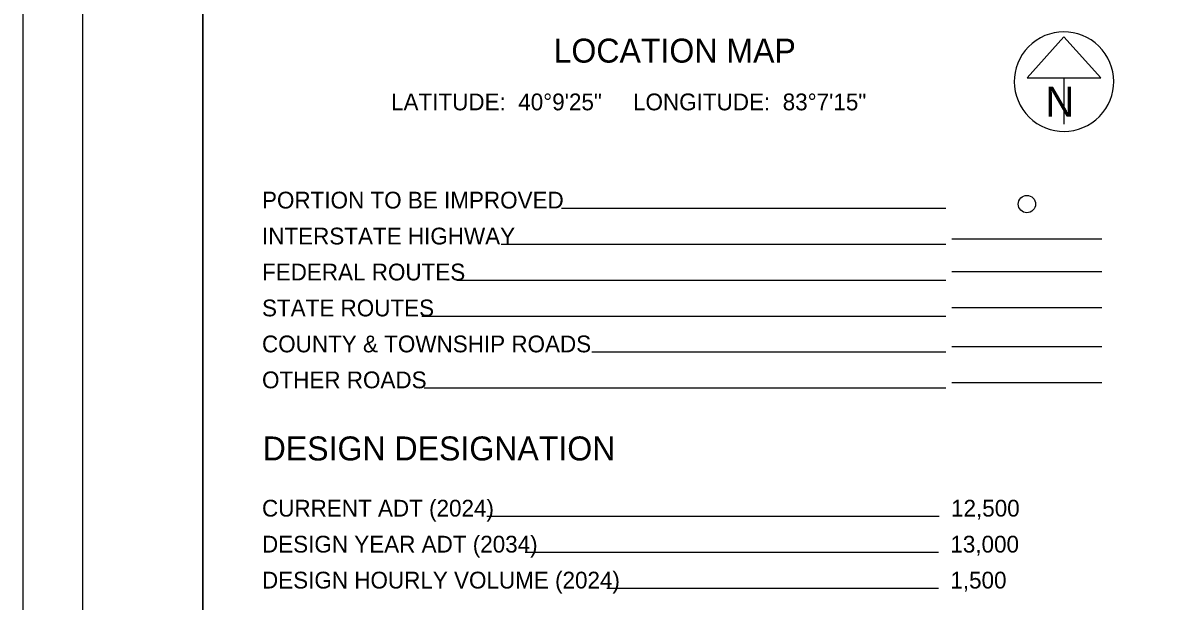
# Model space of a CAD drawing. Extents: x -38.2 to 41.9, y -4 to 24.9.
# Drawn here: x 0 to 9.56, y 9.1 to 13.93 of the extents above; entities that cross this region are included whole.
import ezdxf

# ---------------------------------------------------------------- set-up
doc = ezdxf.new("R2010")
doc.units = 0
for name, color, linetype in [('SH_Border', 7, 'Continuous'), ('SH_Cut_Line', 7, 'Continuous'), ('SH_Data', 7, 'Continuous'), ('SH_Text', 7, 'Continuous')]:
    doc.layers.add(name, color=color, linetype=linetype)

msp = doc.modelspace()

# ---------------------------------------------------------------- linework, layer by layer
at = {"layer": 'SH_Border'}
for points in [[(0.5, 21.5), (1.5, 21.5), (1.5, 0.5), (0.5, 0.5)], [(1.5, 21.5), (33.5, 21.5), (33.5, 0.5), (1.5, 0.5)]]:
    msp.add_lwpolyline(points, close=True, dxfattribs=at)
at = {"layer": 'SH_Cut_Line'}
msp.add_lwpolyline([(0, 0), (34, 0), (34, 22), (0, 22)], close=True, dxfattribs=at)
at = {"layer": 'SH_Data'}
for p, q in [((8.6845, 13.8091), (8.3769, 13.4678)), ((8.9921, 13.4678), (8.6845, 13.8091)), ((8.3769, 13.4678), (8.9921, 13.4678)), ((8.6845, 13.4678), (8.6845, 13.0811)), ((8.6845, 13.4353), (8.6845, 13.4353)), ((8.6845, 13.4353), (8.6845, 13.4353)), ((7.7, 12.3767), (4.4937, 12.3767)), ((7.7, 12.0767), (3.9895, 12.0767)), ((9, 12.1207), (7.75, 12.1207)), ((7.7, 11.7767), (3.6192, 11.7767)), ((9, 11.8491), (7.75, 11.8491)), ((7.7, 11.4767), (3.3288, 11.4767)), ((9, 11.5491), (7.75, 11.5491)), ((9, 11.2223), (7.75, 11.2223)), ((7.7, 11.1767), (4.7452, 11.1767)), ((9, 10.9223), (7.75, 10.9223)), ((7.7, 10.8767), (3.3471, 10.8767)), ((7.6424, 9.8062), (3.871, 9.8062)), ((7.6368, 9.5062), (4.1885, 9.5062)), ((7.6368, 9.2062), (4.8723, 9.2062))]:
    msp.add_line(p, q, dxfattribs=at)
msp.add_circle((8.375, 12.4134), 0.0721, dxfattribs=at)
msp.add_arc((8.6845, 13.4353), 0.4148, 129.77984, 129.76332, dxfattribs=at)

# ---------------------------------------------------------------- texts
for s, height, p in [('N', 0.25, (8.5292, 13.144)), ('DESIGN DESIGNATION', 0.2, (2, 10.2747))]:
    msp.add_text(s, height=height, dxfattribs=at).set_placement(p)
at = {"layer": 'SH_Text'}
for s, height, p in [('LOCATION MAP', 0.2, (4.4269, 13.5938)), ('LATITUDE:  40°9\'25"     LONGITUDE:  83°7\'15"', 0.14, (3.071, 13.1959)), ('PORTION TO BE IMPROVED', 0.14, (1.9944, 12.3767)), ('INTERSTATE HIGHWAY', 0.14, (1.9944, 12.0767)), ('FEDERAL ROUTES', 0.14, (1.9944, 11.7767)), ('STATE ROUTES', 0.14, (1.9944, 11.4767)), ('COUNTY & TOWNSHIP ROADS', 0.14, (1.9944, 11.1767)), ('OTHER ROADS', 0.14, (1.9944, 10.8767)), ('CURRENT ADT (2024)', 0.14, (1.9944, 9.8062)), ('12,500', 0.14, (7.7424, 9.8062)), ('DESIGN YEAR ADT (2034)', 0.14, (1.9944, 9.5062)), ('13,000', 0.14, (7.7368, 9.5062)), ('DESIGN HOURLY VOLUME (2024)', 0.14, (1.9944, 9.2062)), ('1,500', 0.14, (7.7368, 9.2062))]:
    msp.add_text(s, height=height, dxfattribs=at).set_placement(p)

doc.saveas('drawing.dxf')
